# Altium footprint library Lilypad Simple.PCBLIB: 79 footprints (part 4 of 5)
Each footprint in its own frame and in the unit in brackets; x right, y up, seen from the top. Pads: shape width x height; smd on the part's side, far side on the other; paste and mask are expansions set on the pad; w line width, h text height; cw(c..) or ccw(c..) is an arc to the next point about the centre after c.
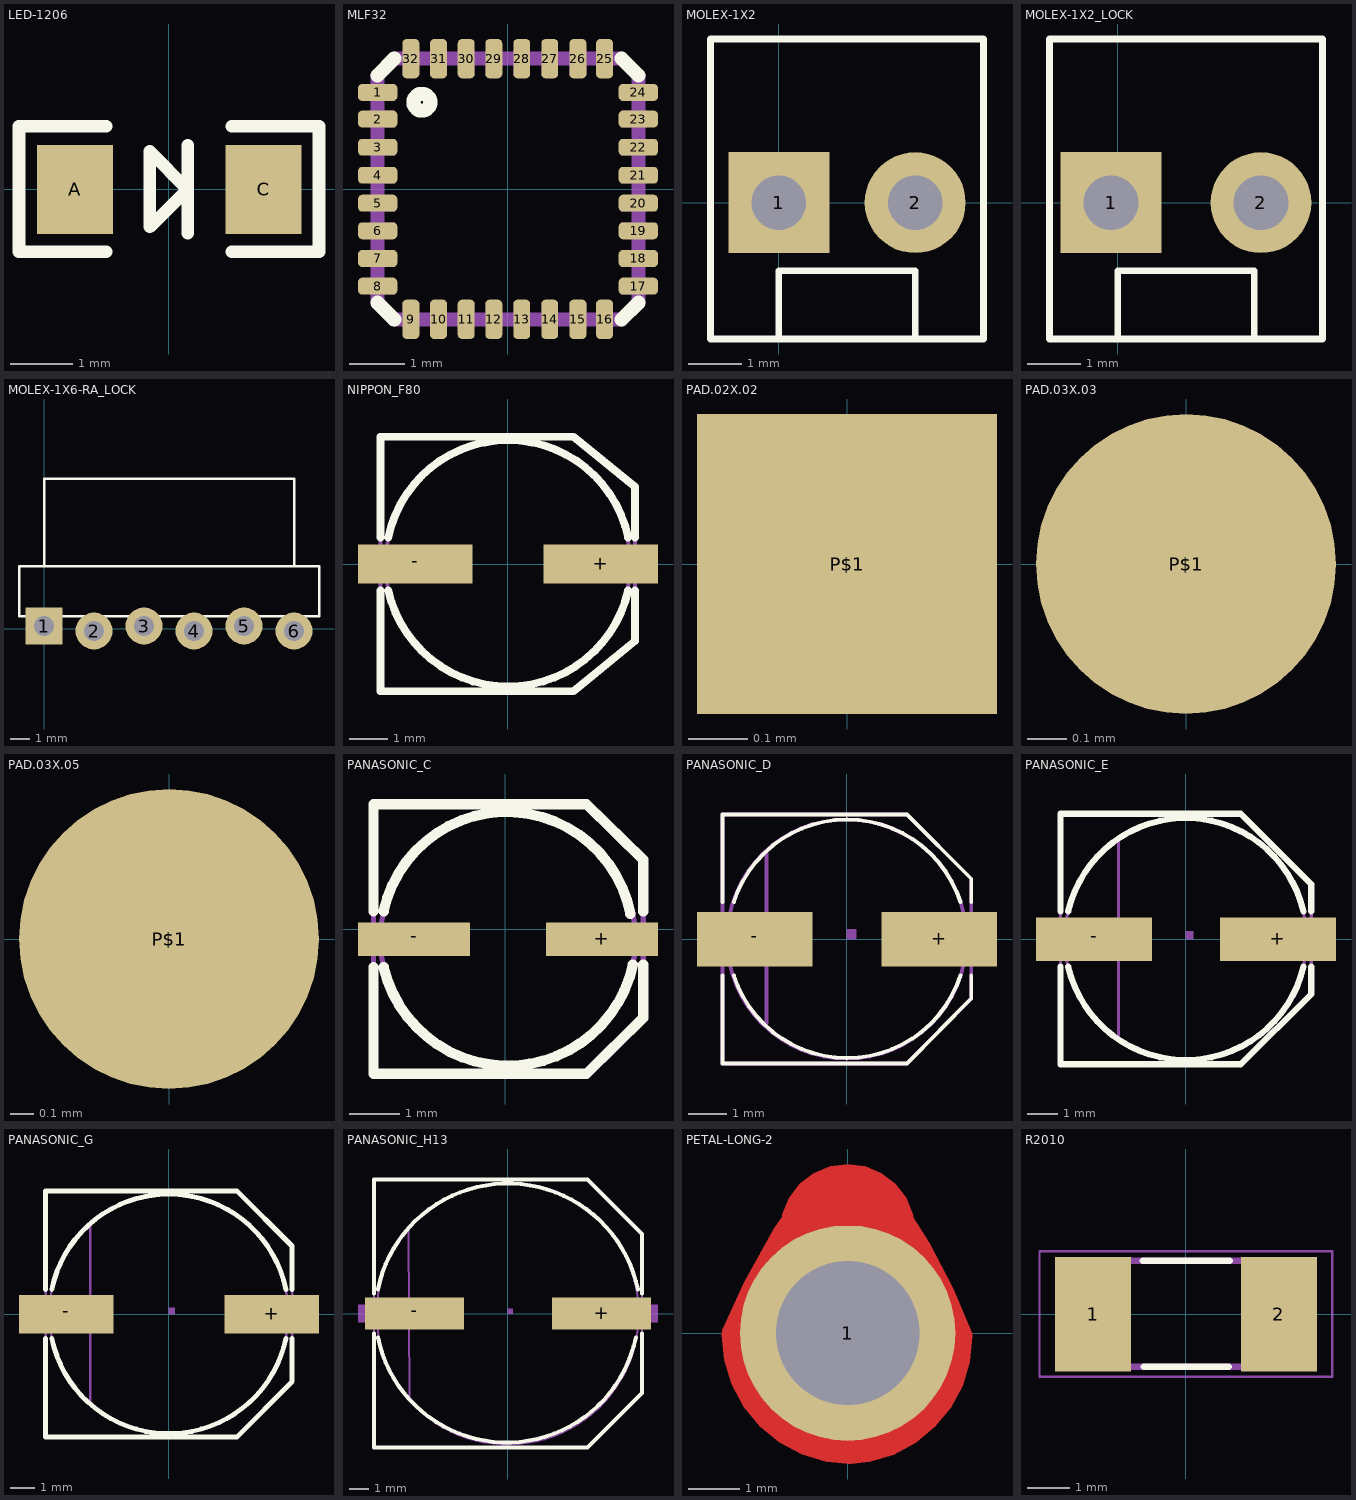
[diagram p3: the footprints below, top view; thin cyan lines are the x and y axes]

## LED-1206 [mil]
pads (2):
  rect 48x56 smd: A(-59.06,0) C(60,0)
Top Overlay:
  lines w8: -39.37,-39.37 -94.49,-39.37 -94.49,40 -39.37,40 ; 12,-27.56 12,0 ; 12,28 12,0 ; 40,-39.37 95,-39.37 95,40 40,40 ; 12,0 -11.81,24 -11.81,-23.62 12,0

## MLF32 [mil]
pads (32):
  rrect50% 28x12 smd: 1(-92.52,69) 2(-92.52,50) 3(-92.52,30) 4(-92.52,10) 5(-92.52,-9.84) 6(-92.52,-29.53) 7(-92.52,-49.21) 8(-92.52,-68.9) 17(93,-68.9) 18(93,-49.21) 19(93,-29.53) 20(93,-9.84) 21(93,10) 22(93,30) 23(93,50) 24(93,69)
  rrect50% 12x28 smd: 9(-68.9,-92.52) 10(-49.21,-92.52) 11(-29.53,-92.52) 12(-9.84,-92.52) 13(10,-92.52) 14(30,-92.52) 15(50,-92.52) 16(69,-92.52) 25(69,93) 26(50,93) 27(30,93) 28(10,93) 29(-9.84,93) 30(-29.53,93) 31(-49.21,93) 32(-68.9,93)
Top Overlay:
  circle w10: c-61.02,62 r6
  lines w10: -92.52,-80.71 -80.71,-92.52 ; -92.52,81 -80.71,93 ; 81,-92.52 93,-80.71 ; 81,93 93,81
Courtyard Bottom:
  rectangle: -98.43,63 -80.71,75
  rectangle: -98.43,44 -80.71,56
  rectangle: -98.43,24 -80.71,36
  rectangle: -98.43,4 -80.71,16
  rectangle: -98.43,-15.75 -80.71,-3.94
  rectangle: -98.43,-35.43 -80.71,-23.62
  rectangle: -98.43,-55.12 -80.71,-43.31
  rectangle: -98.43,-74.8 -80.71,-62.99
  rectangle: -74.8,-98.43 -62.99,-80.71
  rectangle: -55.12,-98.43 -43.31,-80.71
  rectangle: -35.43,-98.43 -23.62,-80.71
  rectangle: -15.75,-98.43 -3.94,-80.71
  rectangle: 4,-98.43 16,-80.71
  rectangle: 24,-98.43 36,-80.71
  rectangle: 44,-98.43 56,-80.71
  rectangle: 63,-98.43 75,-80.71
  rectangle: 81,-74.8 99,-62.99
  rectangle: 81,-55.12 99,-43.31
  rectangle: 81,-35.43 99,-23.62
  rectangle: 81,-15.75 99,-3.94
  rectangle: 81,4 99,16
  rectangle: 81,24 99,36
  rectangle: 81,44 99,56
  rectangle: 81,63 99,75
  rectangle: 63,81 75,99
  rectangle: 44,81 56,99
  rectangle: 24,81 36,99
  rectangle: 4,81 16,99
  rectangle: -15.75,81 -3.94,99
  rectangle: -35.43,81 -23.62,99
  rectangle: -55.12,81 -43.31,99
  rectangle: -74.8,81 -62.99,99
  lines w10: -92.52,-80.71 -92.52,81 ; -80.71,-92.52 81,-92.52 ; -80.71,93 81,93 ; 93,-80.71 93,81

## MOLEX-1X2 [mil]
pads (2):
  rect 74x74 hole 40: 1(0,0)
  round 74 hole 40: 2(100,0)
Top Overlay:
  lines w5: 0,-100 100,-100 ; 0,-100 -50,-100 -50,120 150,120 150,-100 100,-100 ; 0,-100 0,-50 100,-50 100,-100

## MOLEX-1X2_LOCK [mil]
pads (2):
  rect 74x74 hole 40: 1(-5,0)
  round 74 hole 40: 2(105,0)
Top Overlay:
  lines w5: 0,-100 100,-100 ; 0,-100 -50,-100 -50,120 150,120 150,-100 100,-100 ; 0,-100 0,-50 100,-50 100,-100
Courtyard Bottom:
  rectangle: -11.5,-11.5 12,12
  rectangle: 89,-11.5 112,12

## MOLEX-1X6-RA_LOCK [mil]
pads (6):
  rect 74x74 hole 40: 1(0,5)
  round 74 hole 40: 2(100,-5) 3(200,5) 4(300,-5) 5(400,5) 6(500,-5)
Top Overlay:
  lines w5: 0,125 500,125 ; 0,125 -50,125 -50,25 550,25 550,125 500,125 ; 0,125 0,300 500,300 500,125

## NIPPON_F80 [mil]
pads (2):
  rect 117x40 smd: +(95,0) -(-94.49,0)
Top Overlay:
  lines w8: -129.92,-26.97 -129.92,-129.92 67,-129.92 130,-78.74 130,-26.97 ; -129.92,27 -129.92,130 67,130 130,79 130,27 ; -122.05,-26.97 ccw(c0.48,0.48) 123,-26.97 ; -122.05,27 cw(c0.48,1.52) 123,27
Courtyard Bottom:
  circle w4: c0,0 r125
  lines w4: -129.92,-129.92 67,-129.92 130,-78.74 130,79 67,130 -129.92,130 -129.92,-129.92

## PAD.02X.02 [mil]
pads (1):
  rect 20x20 smd: P$1(0,0)

## PAD.03X.03 [mil]
pads (1):
  rrect100% 30x30 smd: P$1(0,0)

## PAD.03X.05 [mil]
pads (1):
  rrect100% 50x50 smd: P$1(0,0)

## PANASONIC_C [mil]
pads (2):
  rect 87x26 smd: +(75,-7.87) -(-70.87,-7.87)
Top Overlay:
  lines w8: -102.36,-29.53 -102.36,-112.2 63,-112.2 107,-68.9 107,-27.56 ; -102.36,14 -102.36,97 63,97 107,54 107,14 ; -94.49,-29.53 ccw(c2.03,-6.83) 99,-27.56 ; -94.49,14 cw(c1.05,-6.74) 97,12
Courtyard Bottom:
  circle w4: c2,-7.87 r99
  lines w4: -102.36,-112.2 63,-112.2 107,-68.9 107,54 63,97 -102.36,97 -102.36,-112.2

## PANASONIC_D [mil]
pads (2):
  rect 119x56 smd: +(95,0) -(-94.49,0)
Top Overlay:
  lines w4: -127.95,-37.4 -127.95,-127.95 62,-127.95 128,-61.02 128,-37.4 ; -127.95,38 -127.95,128 62,128 128,62 128,38 ; -116.14,-37.4 ccw(c0.43,0.14) 117,-37.4 ; -116.14,38 cw(c0.43,0.46) 117,38
Courtyard Bottom:
  circle w4: c0,0 r123
  rectangle: -143.7,-13.78 -120.08,14
  rectangle: 121,-13.78 144,14
  region: 0,0 10,0 10,10 0,10
  lines w4: -82.68,-86.61 -82.68,89 ; -127.95,-127.95 62,-127.95 128,-61.02 128,62 62,128 -127.95,128 -127.95,-127.95

## PANASONIC_E [mil]
pads (2):
  rect 150x56 smd: +(119,0) -(-118.11,0)
Top Overlay:
  lines w8: -161.42,-35.43 -161.42,-161.42 71,-161.42 162,-70.87 162,-35.43 ; -161.42,36 -161.42,162 71,162 162,71 162,36 ; -151.57,-35.43 ccw(c0.21,0.05) 152,-35.43 ; -151.57,36 cw(c0.21,0.52) 152,36
Courtyard Bottom:
  circle w4: c0,0 r156
  rectangle: -177.17,-13.78 -149.61,14
  rectangle: 150,-13.78 178,14
  region: 0,0 10,0 10,10 0,10
  lines w4: -86.61,-127.95 -86.61,128 ; -161.42,-161.42 71,-161.42 162,-70.87 162,71 71,162 -161.42,162 -161.42,-161.42

## PANASONIC_G [mil]
pads (2):
  rect 154x63 smd: +(168,0) -(-167.32,0)
Top Overlay:
  lines w8: -200.79,-39.37 -200.79,-200.79 111,-200.79 201,-110.24 201,-39.37 ; -200.79,40 -200.79,201 111,201 201,111 201,40 ; -190.94,-39.37 ccw(c0.03,0.01) 191,-39.37 ; -190.94,40 cw(c0.03,0.62) 191,40
Courtyard Bottom:
  circle w4: c0,0 r195
  rectangle: -230.31,-17.72 -192.91,18
  rectangle: 193,-17.72 231,18
  region: 0,0 10,0 10,10 0,10
  lines w4: -127.95,-143.7 -127.95,146 ; -200.79,-200.79 111,-200.79 201,-110.24 201,111 111,201 -200.79,201 -200.79,-200.79

## PANASONIC_H13 [mil]
pads (2):
  rect 197x63 smd: +(186,0) -(-185.04,0)
Top Overlay:
  lines w8: -265.75,-39.37 -265.75,-265.75 158,-265.75 266,-157.48 266,-39.37 ; -265.75,40 -265.75,266 158,266 266,158 266,40 ; -257.87,-47.24 ccw(c-1.94,5.54) 254,-47.24 ; -257.87,48 cw(c0.06,-5.19) 258,48
Courtyard Bottom:
  circle w4: c0,0 r260
  rectangle: -297.24,-17.72 -259.84,18
  rectangle: 260,-17.72 298,18
  region: 0,0 10,0 10,10 0,10
  lines w4: -196.85,168 -194.88,-171.26 ; -265.75,-265.75 158,-265.75 266,-157.48 266,158 158,266 -265.75,266 -265.75,-265.75

## PETAL-LONG-2 [mil]
pads (1):
  round 165 hole 110: 1(0,0)
Top Layer:
  region: -50.12,89.07 -56.05,80.2 -79.1,39.04 -96.13,2.1 -96.13,2.01 -96.43,-1.06 -94.52,-20.47 -88.86,-39.12 -79.67,-56.32 -67.3,-71.39 -52.23,-83.76 -35.03,-92.95 -16.37,-98.61 -0.01,-100.23 0.01,-100.28 16.93,-98.62 35.24,-93.06 52.11,-84.04 66.9,-71.9 79.04,-57.11 88.06,-40.24 93.62,-21.93 95.49,-2.89 95.29,-0.78 95.32,-0.67 80.97,33.99 62.66,69.15 50.01,89.01 50.2,89.05 49.93,91.14 44.76,103.6 36.55,114.31 25.84,122.52 13.38,127.69 0,129.45 -13.38,127.69 -25.84,122.52 -36.55,114.31 -44.76,103.6 -49.93,91.14 -50.2,89.05
Top Solder:
  region: -50.12,89.07 -56.05,80.2 -79.1,39.04 -96.13,2.1 -96.13,2.01 -96.43,-1.06 -94.52,-20.47 -88.86,-39.12 -79.67,-56.32 -67.3,-71.39 -52.23,-83.76 -35.03,-92.95 -16.37,-98.61 -0.01,-100.23 0.01,-100.28 16.93,-98.62 35.24,-93.06 52.11,-84.04 66.9,-71.9 79.04,-57.11 88.06,-40.24 93.62,-21.93 95.49,-2.89 95.29,-0.78 95.32,-0.67 80.97,33.99 62.66,69.15 50.01,89.01 50.2,89.05 49.93,91.14 44.76,103.6 36.55,114.31 25.84,122.52 13.38,127.69 0,129.45 -13.38,127.69 -25.84,122.52 -36.55,114.31 -44.76,103.6 -49.93,91.14 -50.2,89.05

## R2010 [mil]
pads (2):
  rect 71x107 smd: 1(-86.61,0) 2(87,0)
Top Overlay:
  lines w6: -40.43,50 41,50 ; -39.45,-49.02 40,-49.02
Courtyard Bottom:
  rectangle: 65,-52 99,53
  rectangle: -98,-52 -64.54,53
  lines w6: -65.43,50 66,50 ; -64.45,-49.02 67,-49.02
Mechanical 37:
  lines w2: -136.73,-58.39 -136.73,59 137,59 137,-58.39 -136.73,-58.39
